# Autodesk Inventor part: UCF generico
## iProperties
Author: Administrator
Shininess: 30.0
PropertySet Name: _Private Model Information
Length Units: 11269
Angle Units: 11283
Time Units: 11279
Mass Units: 11290
Length Display Precision: 3
Angle Display Precision: 2
Compacted: True
Created: 2001-07
Part Number: UCF generico
Document SubType Name: Modellazione
Designer: Administrator
Control State: 0
Master: False
Checked Out: False
PropertySet Name: Design Tracking Control
Density: 0.0
Volumn: 0.0
Area: 0.0
PropertySet Name: Model Information
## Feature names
1. Estrusione1 [Extrusion]
2. Raccordo1 [Fillet]
3. Estrusione2 [Extrusion]
4. Estrusione3 [Extrusion]
5. Raccordo2 [Fillet]
6. Raccordo3 [Fillet]
7. Raccordo4 [Fillet]
8. Raccordo8 [Fillet]
9. Foro1 [Hole]
10. Estrusione4 [Extrusion]
11. Raccordo5 [Fillet]
12. Rivoluzione5 [Revolution]
13. Rivoluzione6 [Revolution]
14. Raccordo7 [Fillet]
15. Rivoluzione7 [Revolution]
16. Foro5 [Hole]
17. Serie circolare4 [Circular Pattern]
18. Rivoluzione8 [Revolution]
19. Serie circolare5 [Circular Pattern]
